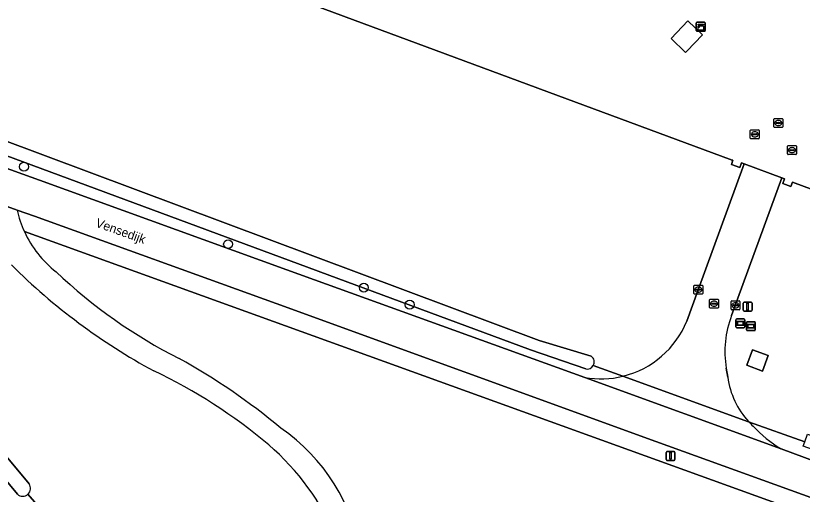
# Model space of a CAD drawing. Extents: x 156061 to 157804, y 383437 to 385640.
# Drawn here: x 156631.9 to 156720, y 385027.7 to 385081.3 of the extents above; entities that cross this region are included whole.
import ezdxf

# ---------------------------------------------------------------- set-up
doc = ezdxf.new("R2010")
doc.units = 0
for name, color, linetype in [('IMGEO_Berm_groen', 7, 'Continuous'), ('IMGEO_Boom', 7, 'Continuous'), ('IMGEO_Erf', 7, 'Continuous'), ('IMGEO_Grasland_overig', 7, 'Continuous'), ('IMGEO_Groenvoorziening', 7, 'Continuous'), ('IMGEO_Hek', 7, 'Continuous'), ('IMGEO_Informatiebord', 7, 'Continuous'), ('IMGEO_Kast', 7, 'Continuous'), ('IMGEO_Kolk', 7, 'Continuous'), ('IMGEO_Lage_trafo', 7, 'Continuous'), ('IMGEO_Lichtmast', 7, 'Continuous'), ('IMGEO_Loofbos', 7, 'Continuous'), ('IMGEO_Openbare_ruimte_label', 7, 'Continuous'), ('IMGEO_Pand', 7, 'Continuous'), ('IMGEO_Rijbaan_lokaal_open', 7, 'Continuous'), ('IMGEO_Rioolput', 7, 'Continuous'), ('IMGEO_Waterloop', 7, 'Continuous')]:
    doc.layers.add(name, color=color, linetype=linetype)

msp = doc.modelspace()

# ---------------------------------------------------------------- linework, layer by layer
at = {"layer": 'IMGEO_Berm_groen'}
for points in [[(156632.123, 385027.749), (156617.114, 385045.869)], [(156635.536, 385025.155), (156633.293, 385027.733)]]:
    msp.add_lwpolyline(points, dxfattribs=at)
msp.add_arc((156632.717, 385028.385), 0.87, 226.97116, 311.46187, dxfattribs=at)
at = {"layer": 'IMGEO_Boom'}
for centre in [(156632.856, 385064.382), (156655.692, 385055.706), (156670.884, 385050.847), (156676.018, 385048.942)]:
    msp.add_circle(centre, 0.489, dxfattribs=at)
at = {"layer": 'IMGEO_Erf'}
msp.add_lwpolyline([(156729.501, 385186.702), (156715.502, 385172.106), (156680.122, 385135.301), (156684.801, 385133.044), (156658.244, 385085.094), (156712.128, 385065.114), (156712.188, 385065.092), (156712.024, 385064.637), (156712.959, 385064.3), (156713.142, 385064.807), (156713.445, 385064.694), (156717.677, 385063.118), (156717.97, 385063.009), (156717.781, 385062.506), (156718.696, 385062.163), (156718.88, 385062.654), (156870.373, 385006.508), (156870.967, 385006.288), (156875.119, 385016.625), (156892.549, 385064.295), (156865.99, 385088.285), (156852.111, 385101.789), (156804.773, 385147.48), (156780.437, 385174.157)], dxfattribs=at)
msp.add_lwpolyline([(156706.903, 385077.152), (156705.294, 385078.733), (156707.151, 385080.707), (156708.792, 385079.128), (156707.045, 385077.298)], close=True, dxfattribs=at)
at = {"layer": 'IMGEO_Grasland_overig'}
msp.add_lwpolyline([(156632.086, 385059.534), (156628.997, 385060.649), (156628.988, 385058.529), (156628.983, 385057.433)], dxfattribs=at)
for centre, radius, start, end in [((156643.914, 385062.172), 12.118, 192.57556, 204.6773), ((156643.961, 385062.187), 12.167, 204.64837, 231.85835), ((156680.809, 385103.134), 70.085, 225.22503, 241.50853), ((156676.67, 385095.125), 58.522, 226.58108, 243.14024), ((156613.824, 384977.458), 74.902, 50.35651, 60.91962), ((156621.297, 384986.787), 60.645, 50.02945, 64.52979), ((156649.497, 385017.591), 21.32, 8.76662, 55.37233), ((156641.331, 385011.478), 28.857, 23.28741, 49.02038)]:
    msp.add_arc(centre, radius, start, end, dxfattribs=at)
at = {"layer": 'IMGEO_Groenvoorziening'}
for points in [[(156707.035, 385047.107), (156708.324, 385050.618), (156713.445, 385064.694), (156713.142, 385064.807), (156712.959, 385064.3), (156712.024, 385064.637), (156712.188, 385065.092), (156712.128, 385065.114), (156658.244, 385085.094), (156573.383, 385116.706), (156605.74, 385212.859), (156607.972, 385218.584), (156610.728, 385223.591), (156612.435, 385226.054), (156614.37, 385228.412), (156616.518, 385230.465), (156619.083, 385232.209), (156621.743, 385233.409), (156624.697, 385234.463), (156627.701, 385235.066), (156633.775, 385235.979), (156633.506, 385237.044), (156622.494, 385234.266)], [(156780.437, 385174.157), (156804.773, 385147.48), (156852.111, 385101.789), (156865.99, 385088.285), (156892.549, 385064.295), (156875.119, 385016.625), (156870.967, 385006.288), (156870.373, 385006.508), (156718.88, 385062.654), (156718.696, 385062.163), (156717.781, 385062.506), (156717.97, 385063.009), (156717.677, 385063.118), (156712.05, 385047.718)], [(156695.717, 385041.754), (156689.552, 385043.906), (156629.599, 385066.068), (156629.792, 385066.728), (156607.493, 385074.38), (156566.301, 385089.228)], [(156566.301, 385089.228), (156607.493, 385074.38), (156629.792, 385066.728), (156630.025, 385067.527), (156690.519, 385044.949), (156696.349, 385043.188)], [(156569.753, 385086.114), (156604.139, 385073.809), (156606.916, 385072.811), (156634.591, 385062.861), (156662.26, 385052.848), (156695.623, 385040.804)], [(156713.959, 385035.854), (156720.234, 385033.587), (156720.551, 385034.44), (156728.196, 385031.696), (156816.114, 385000), (156861.261, 384983.568), (156860.901, 384982.658), (156861.085, 384982.587), (156860.328, 384980.642), (156901.609, 384965.447), (156912.384, 384961.462), (156912.863, 384962.751), (156905.319, 384965.341), (156869.874, 384978.487), (156870.004, 384979.135), (156868.867, 384979.575), (156871.034, 384985.236), (156899.441, 385059.57)], [(156703.574, 385033.623), (156661.061, 385049.074), (156634.022, 385058.832), (156632.086, 385059.534)], [(156632.902, 385057.113), (156756.361, 385012.544), (156799.556, 384996.608), (156799.568, 384997.323), (156799.577, 384998.038), (156799.582, 384998.753), (156796.159, 385000), (156770.015, 385009.525), (156724.41, 385026.088), (156703.574, 385033.623)], [(156699.886, 385040.939), (156696.567, 385042.138)], [(156696.567, 385042.138), (156699.886, 385040.939), (156699.908, 385040.944), (156699.931, 385040.95)], [(156711.45, 385041.827), (156711.623, 385040.831)], [(156713.959, 385035.854), (156713.968, 385035.845), (156713.977, 385035.835)], [(156717.591, 385032.815), (156725.727, 385029.794), (156771.273, 385013.259), (156807.534, 385000.027), (156811.247, 384998.672), (156860.328, 384980.642), (156861.085, 384982.587), (156860.901, 384982.658), (156860.751, 384982.28), (156811.97, 385000), (156727.843, 385030.322), (156720.06, 385033.119), (156720.234, 385033.587), (156713.959, 385035.854)]]:
    msp.add_lwpolyline(points, dxfattribs=at)
msp.add_lwpolyline([(156716.143, 385043.251), (156715.495, 385041.518), (156713.757, 385042.168), (156714.405, 385043.901)], close=True, dxfattribs=at)
for centre, radius, start, end in [((156643.914, 385062.172), 12.118, 192.57556, 204.6773), ((156722.451, 385043.683), 11.156, 158.79405, 189.57488), ((156697.431, 385051.011), 10.367, 283.95359, 337.87702), ((156695.873, 385042.542), 0.803, 329.81947, 53.63865), ((156695.873, 385042.541), 0.802, 258.77101, 329.85253), ((156697.433, 385051.017), 10.372, 259.94922, 283.67843), ((156720.643, 385042.028), 9.099, 187.55775, 222.72912), ((156721.113, 385042.501), 9.765, 223.04969, 226.95031), ((156725.28, 385045.508), 14.84, 223.11636, 238.79479)]:
    msp.add_arc(centre, radius, start, end, dxfattribs=at)
at = {"layer": 'IMGEO_Hek'}
for points in [[(156658.244, 385085.094), (156712.128, 385065.114), (156712.188, 385065.092)], [(156713.445, 385064.694), (156713.142, 385064.807)], [(156717.677, 385063.118), (156713.445, 385064.694)], [(156717.97, 385063.009), (156717.677, 385063.118)], [(156718.88, 385062.654), (156870.373, 385006.508)]]:
    msp.add_lwpolyline(points, dxfattribs=at)
at = {"layer": 'IMGEO_Informatiebord'}
for p, q in [((156712.535, 385046.462), (156712.535, 385047.262)), ((156712.535, 385047.262), (156712.535, 385046.462)), ((156712.635, 385047.362), (156713.425, 385047.362)), ((156713.425, 385047.362), (156712.635, 385047.362)), ((156713.525, 385047.262), (156713.525, 385046.462)), ((156713.525, 385046.462), (156713.525, 385047.262)), ((156713.425, 385046.362), (156712.635, 385046.362)), ((156712.635, 385046.362), (156713.425, 385046.362)), ((156713.712, 385046.139), (156713.712, 385046.939)), ((156713.712, 385046.939), (156713.712, 385046.139)), ((156713.812, 385047.039), (156714.602, 385047.039)), ((156714.602, 385047.039), (156713.812, 385047.039)), ((156714.702, 385046.939), (156714.702, 385046.139)), ((156714.702, 385046.139), (156714.702, 385046.939)), ((156714.602, 385046.039), (156713.812, 385046.039)), ((156713.812, 385046.039), (156714.602, 385046.039))]:
    msp.add_line(p, q, dxfattribs=at)
for points in [[(156712.636, 385047.094), (156713.424, 385047.094), (156713.424, 385046.63), (156712.636, 385046.63), (156712.636, 385047.094)], [(156712.701, 385047.029), (156712.701, 385046.695), (156713.359, 385046.695), (156713.359, 385047.029), (156712.701, 385047.029)], [(156713.813, 385046.771), (156714.601, 385046.771), (156714.601, 385046.307), (156713.813, 385046.307), (156713.813, 385046.771)], [(156713.878, 385046.706), (156713.878, 385046.372), (156714.536, 385046.372), (156714.536, 385046.706), (156713.878, 385046.706)]]:
    msp.add_lwpolyline(points, dxfattribs=at)
for centre, start, end in [((156712.635, 385047.262), 90, 180), ((156712.635, 385047.262), 90, 180), ((156713.425, 385047.262), 0, 90), ((156713.425, 385047.262), 360, 90), ((156712.635, 385046.462), 180, 270), ((156712.635, 385046.462), 180, 270), ((156713.425, 385046.462), 270, 0), ((156713.425, 385046.462), 270, 0), ((156713.812, 385046.939), 90, 180), ((156713.812, 385046.939), 90, 180), ((156714.602, 385046.939), 0, 90), ((156714.602, 385046.939), 360, 90), ((156713.812, 385046.139), 180, 270), ((156713.812, 385046.139), 180, 270), ((156714.602, 385046.139), 270, 0), ((156714.602, 385046.139), 270, 0)]:
    msp.add_arc(centre, 0.1, start, end, dxfattribs=at)
at = {"layer": 'IMGEO_Kast'}
for p, q in [((156708.096, 385079.608), (156708.096, 385080.449)), ((156708.096, 385080.449), (156708.096, 385079.608)), ((156708.171, 385080.533), (156709.012, 385080.533)), ((156709.012, 385080.533), (156708.171, 385080.533)), ((156709.096, 385080.458), (156709.096, 385079.617)), ((156709.096, 385079.617), (156709.096, 385080.458)), ((156709.021, 385079.533), (156708.18, 385079.533)), ((156708.18, 385079.533), (156709.021, 385079.533))]:
    msp.add_line(p, q, dxfattribs=at)
for points in [[(156708.291, 385080.323), (156708.891, 385080.323), (156708.891, 385080.238), (156708.291, 385080.238), (156708.291, 385080.323)], [(156708.291, 385080.148), (156708.891, 385080.148), (156708.891, 385079.659), (156708.291, 385079.659), (156708.291, 385080.148)]]:
    msp.add_lwpolyline(points, dxfattribs=at)
msp.add_circle((156708.375, 385079.997), 0.0377, dxfattribs=at)
for centre, start, end in [((156708.174, 385080.455), 92.4484, 184.28452), ((156708.174, 385080.455), 92.4484, 184.28452), ((156709.018, 385080.455), 2.4484, 94.28452), ((156709.018, 385080.455), 2.4484, 94.28452), ((156708.174, 385079.611), 182.4484, 274.28452), ((156708.174, 385079.611), 182.4484, 274.28452), ((156709.018, 385079.611), 272.4484, 4.28452), ((156709.018, 385079.611), 272.4484, 4.28452)]:
    msp.add_arc(centre, 0.0779, start, end, dxfattribs=at)
at = {"layer": 'IMGEO_Kolk'}
for p, q in [((156714.145, 385067.574), (156714.145, 385068.426)), ((156714.22, 385068.5), (156715.072, 385068.5)), ((156715.146, 385068.426), (156715.146, 385067.574)), ((156715.072, 385067.5), (156714.22, 385067.5)), ((156714.404, 385067.994), (156714.404, 385068.006)), ((156714.842, 385067.957), (156714.444, 385067.957)), ((156714.447, 385068.043), (156714.845, 385068.043)), ((156714.656, 385067.72), (156714.631, 385067.72)), ((156714.633, 385068.28), (156714.658, 385068.28)), ((156714.888, 385068.006), (156714.888, 385067.994)), ((156718.312, 385065.807), (156718.312, 385066.659)), ((156718.387, 385066.733), (156719.239, 385066.733)), ((156719.313, 385066.659), (156719.313, 385065.807)), ((156719.239, 385065.733), (156718.387, 385065.733)), ((156718.571, 385066.227), (156718.571, 385066.239)), ((156719.009, 385066.19), (156718.611, 385066.19)), ((156718.614, 385066.276), (156719.012, 385066.276)), ((156718.823, 385065.953), (156718.798, 385065.953)), ((156718.8, 385066.513), (156718.825, 385066.513)), ((156719.055, 385066.239), (156719.055, 385066.227)), ((156707.822, 385050.193), (156707.822, 385051.045)), ((156707.897, 385051.119), (156708.749, 385051.119)), ((156708.31, 385050.899), (156708.335, 385050.899)), ((156708.823, 385051.045), (156708.823, 385050.193)), ((156708.749, 385050.119), (156707.897, 385050.119)), ((156708.081, 385050.613), (156708.081, 385050.625)), ((156708.519, 385050.576), (156708.121, 385050.576)), ((156708.124, 385050.662), (156708.522, 385050.662)), ((156708.333, 385050.339), (156708.308, 385050.339)), ((156708.565, 385050.625), (156708.565, 385050.613)), ((156711.986, 385048.448), (156711.986, 385049.3)), ((156712.061, 385049.374), (156712.913, 385049.374)), ((156712.474, 385049.154), (156712.499, 385049.154)), ((156712.987, 385049.3), (156712.987, 385048.448)), ((156712.913, 385048.374), (156712.061, 385048.374)), ((156712.245, 385048.868), (156712.245, 385048.88)), ((156712.683, 385048.831), (156712.285, 385048.831)), ((156712.288, 385048.917), (156712.686, 385048.917)), ((156712.497, 385048.594), (156712.472, 385048.594)), ((156712.729, 385048.88), (156712.729, 385048.868))]:
    msp.add_line(p, q, dxfattribs=at)
for points in [[(156714.145, 385067.574), (156714.145, 385068.426)], [(156714.22, 385068.5), (156715.072, 385068.5)], [(156715.146, 385068.426), (156715.146, 385067.574)], [(156715.072, 385067.5), (156714.22, 385067.5)], [(156718.312, 385065.807), (156718.312, 385066.659)], [(156718.387, 385066.733), (156719.239, 385066.733)], [(156719.313, 385066.659), (156719.313, 385065.807)], [(156719.239, 385065.733), (156718.387, 385065.733)], [(156707.822, 385050.193), (156707.822, 385051.045)], [(156707.897, 385051.119), (156708.749, 385051.119)], [(156708.823, 385051.045), (156708.823, 385050.193)], [(156708.749, 385050.119), (156707.897, 385050.119)], [(156711.986, 385048.448), (156711.986, 385049.3)], [(156712.061, 385049.374), (156712.913, 385049.374)], [(156712.987, 385049.3), (156712.987, 385048.448)], [(156712.913, 385048.374), (156712.061, 385048.374)]]:
    msp.add_lwpolyline(points, dxfattribs=at)
for centre, radius, start, end in [((156714.222, 385068.424), 0.0765, 91.55205, 178.44795), ((156714.222, 385068.424), 0.0765, 91.55205, 178.44795), ((156715.07, 385068.424), 0.0765, 1.55205, 88.44795), ((156715.07, 385068.424), 0.0765, 1.55205, 88.44795), ((156714.222, 385067.576), 0.0765, 181.55205, 268.44795), ((156714.222, 385067.576), 0.0765, 181.55205, 268.44795), ((156714.444, 385068.003), 0.0403, 85.87752, 175.75265), ((156714.441, 385067.993), 0.0366, 178.93798, 274.71019), ((156714.845, 385068), 0.043, 264.86636, 352.45326), ((156714.849, 385068.005), 0.0386, 1.73085, 96.63898), ((156715.07, 385067.576), 0.0765, 271.55205, 358.44795), ((156715.07, 385067.576), 0.0765, 271.55205, 358.44795), ((156718.389, 385066.657), 0.0765, 91.55205, 178.44795), ((156718.389, 385066.657), 0.0765, 91.55205, 178.44795), ((156719.237, 385066.657), 0.0765, 1.55205, 88.44795), ((156719.237, 385066.657), 0.0765, 1.55205, 88.44795), ((156718.389, 385065.809), 0.0765, 181.55205, 268.44795), ((156718.389, 385065.809), 0.0765, 181.55205, 268.44795), ((156718.611, 385066.236), 0.0403, 85.87752, 175.75265), ((156718.608, 385066.226), 0.0366, 178.93798, 274.71019), ((156719.012, 385066.233), 0.043, 264.86636, 352.45326), ((156719.016, 385066.238), 0.0386, 1.73085, 96.63898), ((156719.237, 385065.809), 0.0765, 271.55205, 358.44795), ((156719.237, 385065.809), 0.0765, 271.55205, 358.44795), ((156707.899, 385051.043), 0.0765, 91.55205, 178.44795), ((156707.899, 385051.043), 0.0765, 91.55205, 178.44795), ((156708.747, 385051.043), 0.0765, 1.55205, 88.44795), ((156708.747, 385051.043), 0.0765, 1.55205, 88.44795), ((156707.899, 385050.195), 0.0765, 181.55205, 268.44795), ((156707.899, 385050.195), 0.0765, 181.55205, 268.44795), ((156708.121, 385050.622), 0.0403, 85.87752, 175.75265), ((156708.118, 385050.612), 0.0366, 178.93798, 274.71019), ((156708.522, 385050.619), 0.043, 264.86636, 352.45326), ((156708.526, 385050.624), 0.0386, 1.73085, 96.63898), ((156708.747, 385050.195), 0.0765, 271.55205, 358.44795), ((156708.747, 385050.195), 0.0765, 271.55205, 358.44795), ((156712.063, 385049.298), 0.0765, 91.55205, 178.44795), ((156712.063, 385049.298), 0.0765, 91.55205, 178.44795), ((156712.911, 385049.298), 0.0765, 1.55205, 88.44795), ((156712.911, 385049.298), 0.0765, 1.55205, 88.44795), ((156712.063, 385048.45), 0.0765, 181.55205, 268.44795), ((156712.063, 385048.45), 0.0765, 181.55205, 268.44795), ((156712.285, 385048.877), 0.0403, 85.87752, 175.75265), ((156712.282, 385048.867), 0.0366, 178.93798, 274.71019), ((156712.686, 385048.874), 0.043, 264.86636, 352.45326), ((156712.69, 385048.879), 0.0386, 1.73085, 96.63898), ((156712.911, 385048.45), 0.0765, 271.55205, 358.44795), ((156712.911, 385048.45), 0.0765, 271.55205, 358.44795)]:
    msp.add_arc(centre, radius, start, end, dxfattribs=at)
for centre, major_axis, ratio, start_param, end_param in [((156714.632, 385068), (-0.387, 0.002), 0.722429, 4.712389, 7.853982), ((156714.657, 385068), (-0.39, 0.002), 0.717154, 1.570796, 4.712389), ((156718.799, 385066.233), (-0.387, 0.002), 0.722429, 4.712389, 7.853982), ((156718.824, 385066.233), (-0.39, 0.002), 0.717154, 1.570796, 4.712389), ((156708.309, 385050.619), (-0.387, 0.002), 0.722429, 4.712389, 7.853982), ((156708.334, 385050.619), (-0.39, 0.002), 0.717154, 1.570796, 4.712389), ((156712.473, 385048.874), (-0.387, 0.002), 0.722429, 4.712389, 7.853982), ((156712.498, 385048.874), (-0.39, 0.002), 0.717154, 1.570796, 4.712389)]:
    msp.add_ellipse(centre, major_axis=major_axis, ratio=ratio, start_param=start_param, end_param=end_param, dxfattribs=at)
at = {"layer": 'IMGEO_Lage_trafo'}
msp.add_lwpolyline([(156716.143, 385043.251), (156714.405, 385043.901), (156713.757, 385042.168), (156715.495, 385041.518)], close=True, dxfattribs=at)
at = {"layer": 'IMGEO_Lichtmast'}
for p, q in [((156713.35, 385048.321), (156713.35, 385049.121)), ((156713.35, 385049.121), (156713.35, 385048.321)), ((156713.45, 385049.221), (156714.24, 385049.221)), ((156714.24, 385049.221), (156713.45, 385049.221)), ((156714.34, 385049.121), (156714.34, 385048.321)), ((156714.34, 385048.321), (156714.34, 385049.121)), ((156714.24, 385048.221), (156713.45, 385048.221)), ((156713.45, 385048.221), (156714.24, 385048.221)), ((156704.719, 385031.623), (156704.719, 385032.423)), ((156704.719, 385032.423), (156704.719, 385031.623)), ((156704.819, 385032.523), (156705.609, 385032.523)), ((156705.609, 385032.523), (156704.819, 385032.523)), ((156705.709, 385032.423), (156705.709, 385031.623)), ((156705.709, 385031.623), (156705.709, 385032.423)), ((156705.609, 385031.523), (156704.819, 385031.523)), ((156704.819, 385031.523), (156705.609, 385031.523))]:
    msp.add_line(p, q, dxfattribs=at)
for points in [[(156713.77, 385049.096), (156713.92, 385049.096), (156713.92, 385048.346), (156713.77, 385048.346), (156713.77, 385049.096)], [(156705.139, 385032.398), (156705.289, 385032.398), (156705.289, 385031.648), (156705.139, 385031.648), (156705.139, 385032.398)]]:
    msp.add_lwpolyline(points, dxfattribs=at)
for centre, start, end in [((156713.45, 385049.121), 90, 180), ((156713.45, 385049.121), 90, 180), ((156714.24, 385049.121), 0, 90), ((156714.24, 385049.121), 360, 90), ((156713.45, 385048.321), 180, 270), ((156713.45, 385048.321), 180, 270), ((156714.24, 385048.321), 270, 0), ((156714.24, 385048.321), 270, 0), ((156704.819, 385032.423), 90, 180), ((156704.819, 385032.423), 90, 180), ((156705.609, 385032.423), 0, 90), ((156705.609, 385032.423), 360, 90), ((156704.819, 385031.623), 180, 270), ((156704.819, 385031.623), 180, 270), ((156705.609, 385031.623), 270, 0), ((156705.609, 385031.623), 270, 0)]:
    msp.add_arc(centre, 0.1, start, end, dxfattribs=at)
at = {"layer": 'IMGEO_Loofbos'}
for points in [[(156799.556, 384996.608), (156756.361, 385012.544), (156632.902, 385057.113)], [(156618.313, 385046.971), (156633.422, 385028.896)], [(156633.293, 385027.733), (156635.536, 385025.155), (156636.06, 385025.295), (156636.53, 385025.02), (156657.082, 385000), (156695.13, 384953.541), (156719.856, 384923.789)]]:
    msp.add_lwpolyline(points, dxfattribs=at)
for centre, radius, start, end in [((156643.961, 385062.187), 12.167, 204.64837, 231.85835), ((156680.809, 385103.134), 70.085, 225.22503, 241.50853), ((156676.67, 385095.125), 58.522, 226.58108, 243.14024), ((156613.824, 384977.458), 74.902, 50.35651, 60.91962), ((156621.297, 384986.787), 60.645, 50.02945, 64.52979), ((156649.497, 385017.591), 21.32, 8.76662, 55.37233), ((156641.331, 385011.478), 28.857, 23.28741, 49.02038), ((156632.716, 385028.386), 0.871, 311.45794, 35.8833)]:
    msp.add_arc(centre, radius, start, end, dxfattribs=at)
at = {"layer": 'IMGEO_Pand'}
msp.add_lwpolyline([(156707.045, 385077.298), (156708.792, 385079.128), (156707.151, 385080.707), (156705.294, 385078.733), (156706.903, 385077.152)], close=True, dxfattribs=at)
at = {"layer": 'IMGEO_Rijbaan_lokaal_open'}
for points in [[(156771.273, 385013.259), (156725.727, 385029.794), (156717.591, 385032.815), (156695.623, 385040.804), (156662.26, 385052.848), (156634.591, 385062.861), (156606.916, 385072.811), (156604.139, 385073.809), (156601.317, 385070.529), (156605.548, 385069.093), (156606.086, 385068.91), (156628.997, 385060.649), (156632.086, 385059.534), (156634.022, 385058.832), (156661.061, 385049.074), (156703.574, 385033.623), (156724.41, 385026.088), (156770.015, 385009.525)], [(156717.677, 385063.118), (156713.445, 385064.694), (156708.324, 385050.618), (156707.035, 385047.107)], [(156712.05, 385047.718), (156717.677, 385063.118)], [(156711.623, 385040.831), (156711.45, 385041.827)], [(156695.623, 385040.804), (156717.591, 385032.815)], [(156699.931, 385040.95), (156699.908, 385040.944), (156699.886, 385040.939), (156713.959, 385035.854)], [(156713.977, 385035.835), (156713.968, 385035.845), (156713.959, 385035.854), (156699.886, 385040.939)]]:
    msp.add_lwpolyline(points, dxfattribs=at)
for centre, radius, start, end in [((156722.451, 385043.683), 11.156, 158.79405, 189.57488), ((156697.431, 385051.011), 10.367, 283.95359, 337.87702), ((156697.433, 385051.017), 10.372, 259.94922, 283.67843), ((156720.643, 385042.028), 9.099, 187.55775, 222.72912), ((156721.113, 385042.501), 9.765, 223.04969, 226.95031), ((156725.28, 385045.508), 14.84, 223.11636, 238.79479)]:
    msp.add_arc(centre, radius, start, end, dxfattribs=at)
at = {"layer": 'IMGEO_Rioolput'}
for p, q in [((156716.779, 385068.846), (156716.779, 385069.698)), ((156716.854, 385069.772), (156717.706, 385069.772)), ((156717.038, 385069.266), (156717.038, 385069.278)), ((156717.081, 385069.315), (156717.479, 385069.315)), ((156717.267, 385069.552), (156717.292, 385069.552)), ((156717.522, 385069.278), (156717.522, 385069.266)), ((156717.78, 385069.698), (156717.78, 385068.846)), ((156717.706, 385068.772), (156716.854, 385068.772)), ((156717.476, 385069.229), (156717.078, 385069.229)), ((156717.29, 385068.992), (156717.265, 385068.992)), ((156709.585, 385048.625), (156709.585, 385049.477)), ((156709.66, 385049.551), (156710.512, 385049.551)), ((156709.844, 385049.045), (156709.844, 385049.057)), ((156710.282, 385049.008), (156709.884, 385049.008)), ((156709.887, 385049.094), (156710.285, 385049.094)), ((156710.073, 385049.331), (156710.098, 385049.331)), ((156710.328, 385049.057), (156710.328, 385049.045)), ((156710.586, 385049.477), (156710.586, 385048.625)), ((156710.512, 385048.551), (156709.66, 385048.551)), ((156710.096, 385048.771), (156710.071, 385048.771))]:
    msp.add_line(p, q, dxfattribs=at)
for points in [[(156716.779, 385068.846), (156716.779, 385069.698)], [(156716.854, 385069.772), (156717.706, 385069.772)], [(156717.78, 385069.698), (156717.78, 385068.846)], [(156717.706, 385068.772), (156716.854, 385068.772)], [(156709.585, 385048.625), (156709.585, 385049.477)], [(156709.66, 385049.551), (156710.512, 385049.551)], [(156710.586, 385049.477), (156710.586, 385048.625)], [(156710.512, 385048.551), (156709.66, 385048.551)]]:
    msp.add_lwpolyline(points, dxfattribs=at)
for centre, radius, start, end in [((156716.856, 385069.696), 0.0765, 91.55205, 178.44795), ((156716.856, 385069.696), 0.0765, 91.55205, 178.44795), ((156717.078, 385069.275), 0.0403, 85.87752, 175.75265), ((156717.075, 385069.265), 0.0366, 178.93798, 274.71019), ((156717.479, 385069.272), 0.043, 264.86636, 352.45326), ((156717.483, 385069.277), 0.0386, 1.73085, 96.63898), ((156717.704, 385069.696), 0.0765, 1.55205, 88.44795), ((156717.704, 385069.696), 0.0765, 1.55205, 88.44795), ((156716.856, 385068.848), 0.0765, 181.55205, 268.44795), ((156716.856, 385068.848), 0.0765, 181.55205, 268.44795), ((156717.704, 385068.848), 0.0765, 271.55205, 358.44795), ((156717.704, 385068.848), 0.0765, 271.55205, 358.44795), ((156709.662, 385049.475), 0.0765, 91.55205, 178.44795), ((156709.662, 385049.475), 0.0765, 91.55205, 178.44795), ((156709.884, 385049.054), 0.0403, 85.87752, 175.75265), ((156709.881, 385049.044), 0.0366, 178.93798, 274.71019), ((156710.285, 385049.051), 0.043, 264.86636, 352.45326), ((156710.289, 385049.056), 0.0386, 1.73085, 96.63898), ((156710.51, 385049.475), 0.0765, 1.55205, 88.44795), ((156710.51, 385049.475), 0.0765, 1.55205, 88.44795), ((156709.662, 385048.627), 0.0765, 181.55205, 268.44795), ((156709.662, 385048.627), 0.0765, 181.55205, 268.44795), ((156710.51, 385048.627), 0.0765, 271.55205, 358.44795), ((156710.51, 385048.627), 0.0765, 271.55205, 358.44795)]:
    msp.add_arc(centre, radius, start, end, dxfattribs=at)
for centre, major_axis, ratio, start_param, end_param in [((156717.266, 385069.272), (-0.387, 0.002), 0.722429, 4.712389, 7.853982), ((156717.291, 385069.272), (-0.39, 0.002), 0.717154, 1.570796, 4.712389), ((156710.072, 385049.051), (-0.387, 0.002), 0.722429, 4.712389, 7.853982), ((156710.097, 385049.051), (-0.39, 0.002), 0.717154, 1.570796, 4.712389)]:
    msp.add_ellipse(centre, major_axis=major_axis, ratio=ratio, start_param=start_param, end_param=end_param, dxfattribs=at)
at = {"layer": 'IMGEO_Waterloop'}
for points in [[(156630.025, 385067.527), (156629.792, 385066.728), (156629.599, 385066.068), (156689.552, 385043.906), (156695.717, 385041.754)], [(156696.349, 385043.188), (156690.519, 385044.949), (156630.025, 385067.527)], [(156633.422, 385028.896), (156618.313, 385046.971)], [(156617.114, 385045.869), (156632.123, 385027.749)]]:
    msp.add_lwpolyline(points, dxfattribs=at)
for centre, radius, start, end in [((156695.873, 385042.542), 0.803, 329.81947, 53.63865), ((156695.873, 385042.541), 0.802, 258.77101, 329.85253), ((156632.716, 385028.386), 0.871, 311.45794, 35.8833), ((156632.717, 385028.385), 0.87, 226.97116, 311.46187)]:
    msp.add_arc(centre, radius, start, end, dxfattribs=at)

# ---------------------------------------------------------------- texts
at = {"layer": 'IMGEO_Openbare_ruimte_label'}
msp.add_text('Vensedijk', height=1, rotation=340.18819, dxfattribs=at).set_placement((156640.795, 385057.695))

doc.saveas('drawing.dxf')
